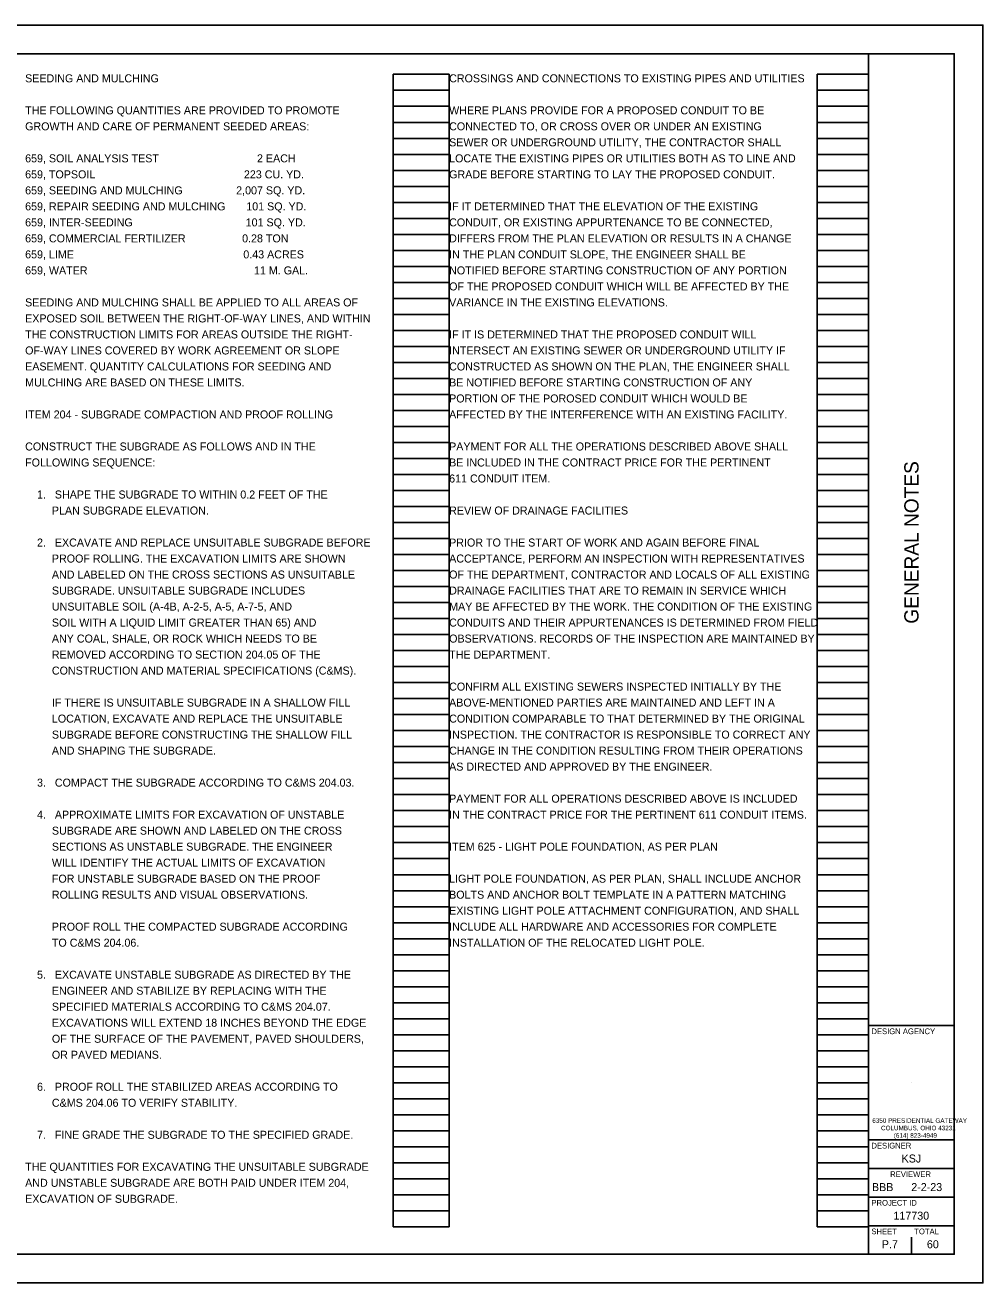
# Model space of a CAD drawing. Extents: x 0 to 68, y 0 to 44.
# Drawn here: x 34.48 to 68, y 0 to 44 of the extents above; entities that cross this region are included whole.
import ezdxf

# ---------------------------------------------------------------- set-up
doc = ezdxf.new("R2010")
doc.units = 0
for name, color, linetype in [('SH_Border', 7, 'Continuous'), ('SH_Cut_Line', 7, 'Continuous'), ('SH_Data', 7, 'Continuous'), ('SH_Text', 7, 'Continuous')]:
    doc.layers.add(name, color=color, linetype=linetype)

msp = doc.modelspace()

# ---------------------------------------------------------------- linework, layer by layer
at = {"layer": 'SH_Border'}
for p, q in [((64, 1), (64, 43)), ((64, 9), (67, 9)), ((64, 5), (67, 5)), ((64, 4), (67, 4)), ((64, 3), (67, 3)), ((64, 2), (67, 2))]:
    msp.add_line(p, q, dxfattribs=at)
msp.add_lwpolyline([(3, 43), (67, 43), (67, 1), (3, 1)], close=True, dxfattribs=at)
at = {"layer": 'SH_Cut_Line'}
msp.add_lwpolyline([(0, 0), (68, 0), (68, 44), (0, 44)], close=True, dxfattribs=at)
at = {"layer": 'SH_Data'}
for p, q in [((47.36, 1.96), (47.36, 42.28)), ((47.36, 42.28), (49.32, 42.28)), ((49.32, 1.96), (49.32, 42.28)), ((62.2, 1.96), (62.2, 42.28)), ((62.2, 42.28), (64, 42.28)), ((64, 1.96), (64, 42.28)), ((47.36, 41.72), (49.32, 41.72)), ((62.2, 41.72), (64, 41.72)), ((47.36, 41.16), (49.32, 41.16)), ((62.2, 41.16), (64, 41.16)), ((47.36, 40.6), (49.32, 40.6)), ((62.2, 40.6), (64, 40.6)), ((47.36, 40.04), (49.32, 40.04)), ((62.2, 40.04), (64, 40.04)), ((47.36, 39.48), (49.32, 39.48)), ((62.2, 39.48), (64, 39.48)), ((47.36, 38.92), (49.32, 38.92)), ((62.2, 38.92), (64, 38.92)), ((47.36, 38.36), (49.32, 38.36)), ((62.2, 38.36), (64, 38.36)), ((47.36, 37.8), (49.32, 37.8)), ((62.2, 37.8), (64, 37.8)), ((47.36, 37.24), (49.32, 37.24)), ((62.2, 37.24), (64, 37.24)), ((47.36, 36.68), (49.32, 36.68)), ((62.2, 36.68), (64, 36.68)), ((47.36, 36.12), (49.32, 36.12)), ((62.2, 36.12), (64, 36.12)), ((47.36, 35.56), (49.32, 35.56)), ((62.2, 35.56), (64, 35.56)), ((47.36, 35), (49.32, 35)), ((62.2, 35), (64, 35)), ((47.36, 34.44), (49.32, 34.44)), ((62.2, 34.44), (64, 34.44)), ((47.36, 33.88), (49.32, 33.88)), ((62.2, 33.88), (64, 33.88)), ((47.36, 33.32), (49.32, 33.32)), ((62.2, 33.32), (64, 33.32)), ((47.36, 32.76), (49.32, 32.76)), ((62.2, 32.76), (64, 32.76)), ((47.36, 32.2), (49.32, 32.2)), ((62.2, 32.2), (64, 32.2)), ((47.36, 31.64), (49.32, 31.64)), ((62.2, 31.64), (64, 31.64)), ((47.36, 31.08), (49.32, 31.08)), ((62.2, 31.08), (64, 31.08)), ((47.36, 30.52), (49.32, 30.52)), ((62.2, 30.52), (64, 30.52)), ((47.36, 29.96), (49.32, 29.96)), ((62.2, 29.96), (64, 29.96)), ((47.36, 29.4), (49.32, 29.4)), ((62.2, 29.4), (64, 29.4)), ((47.36, 28.84), (49.32, 28.84)), ((62.2, 28.84), (64, 28.84)), ((47.36, 28.28), (49.32, 28.28)), ((62.2, 28.28), (64, 28.28)), ((47.36, 27.72), (49.32, 27.72)), ((62.2, 27.72), (64, 27.72)), ((47.36, 27.16), (49.32, 27.16)), ((62.2, 27.16), (64, 27.16)), ((47.36, 26.6), (49.32, 26.6)), ((62.2, 26.6), (64, 26.6)), ((47.36, 26.04), (49.32, 26.04)), ((62.2, 26.04), (64, 26.04)), ((47.36, 25.48), (49.32, 25.48)), ((62.2, 25.48), (64, 25.48)), ((47.36, 24.92), (49.32, 24.92)), ((62.2, 24.92), (64, 24.92)), ((47.36, 24.36), (49.32, 24.36)), ((62.2, 24.36), (64, 24.36)), ((47.36, 23.8), (49.32, 23.8)), ((62.2, 23.8), (64, 23.8)), ((47.36, 23.24), (49.32, 23.24)), ((62.2, 23.24), (64, 23.24)), ((47.36, 22.68), (49.32, 22.68)), ((62.2, 22.68), (64, 22.68)), ((47.36, 22.12), (49.32, 22.12)), ((62.2, 22.12), (64, 22.12)), ((47.36, 21.56), (49.32, 21.56)), ((62.2, 21.56), (64, 21.56)), ((47.36, 21), (49.32, 21)), ((62.2, 21), (64, 21)), ((47.36, 20.44), (49.32, 20.44)), ((62.2, 20.44), (64, 20.44)), ((47.36, 19.88), (49.32, 19.88)), ((62.2, 19.88), (64, 19.88)), ((47.36, 19.32), (49.32, 19.32)), ((62.2, 19.32), (64, 19.32)), ((47.36, 18.76), (49.32, 18.76)), ((62.2, 18.76), (64, 18.76)), ((47.36, 18.2), (49.32, 18.2)), ((62.2, 18.2), (64, 18.2)), ((47.36, 17.64), (49.32, 17.64)), ((62.2, 17.64), (64, 17.64)), ((47.36, 17.08), (49.32, 17.08)), ((62.2, 17.08), (64, 17.08)), ((47.36, 16.52), (49.32, 16.52)), ((62.2, 16.52), (64, 16.52)), ((47.36, 15.96), (49.32, 15.96)), ((62.2, 15.96), (64, 15.96)), ((47.36, 15.4), (49.32, 15.4)), ((62.2, 15.4), (64, 15.4)), ((47.36, 14.84), (49.32, 14.84)), ((62.2, 14.84), (64, 14.84)), ((47.36, 14.28), (49.32, 14.28)), ((62.2, 14.28), (64, 14.28)), ((47.36, 13.72), (49.32, 13.72)), ((62.2, 13.72), (64, 13.72)), ((47.36, 13.16), (49.32, 13.16)), ((62.2, 13.16), (64, 13.16)), ((47.36, 12.6), (49.32, 12.6)), ((62.2, 12.6), (64, 12.6)), ((47.36, 12.04), (49.32, 12.04)), ((62.2, 12.04), (64, 12.04)), ((47.36, 11.48), (49.32, 11.48)), ((62.2, 11.48), (64, 11.48)), ((47.36, 10.92), (49.32, 10.92)), ((62.2, 10.92), (64, 10.92)), ((47.36, 10.36), (49.32, 10.36)), ((62.2, 10.36), (64, 10.36)), ((47.36, 9.8), (49.32, 9.8)), ((62.2, 9.8), (64, 9.8)), ((47.36, 9.24), (49.32, 9.24)), ((62.2, 9.24), (64, 9.24)), ((47.36, 8.68), (49.32, 8.68)), ((62.2, 8.68), (64, 8.68)), ((47.36, 8.12), (49.32, 8.12)), ((62.2, 8.12), (64, 8.12)), ((47.36, 7.56), (49.32, 7.56)), ((62.2, 7.56), (64, 7.56)), ((47.36, 7), (49.32, 7)), ((62.2, 7), (64, 7)), ((65.5, 7), (65.5, 7)), ((47.36, 6.44), (49.32, 6.44)), ((62.2, 6.44), (64, 6.44)), ((47.36, 5.88), (49.32, 5.88)), ((62.2, 5.88), (64, 5.88)), ((47.36, 5.32), (49.32, 5.32)), ((62.2, 5.32), (64, 5.32)), ((47.36, 4.76), (49.32, 4.76)), ((62.2, 4.76), (64, 4.76)), ((47.36, 4.2), (49.32, 4.2)), ((62.2, 4.2), (64, 4.2)), ((47.36, 3.64), (49.32, 3.64)), ((62.2, 3.64), (64, 3.64)), ((47.36, 3.08), (49.32, 3.08)), ((62.2, 3.08), (64, 3.08)), ((47.36, 2.52), (49.32, 2.52)), ((62.2, 2.52), (64, 2.52)), ((47.36, 1.96), (49.32, 1.96)), ((62.2, 1.96), (64, 1.96)), ((64.75, 1.35), (64.75, 1.35)), ((65.5, 1), (65.5, 1.6))]:
    msp.add_line(p, q, dxfattribs=at)
at = {"layer": 'SH_Text'}
msp.add_line((64, 9), (67, 9), dxfattribs=at)

# ---------------------------------------------------------------- texts
at = {"layer": 'SH_Data'}
msp.add_text('GENERAL NOTES', height=0.5, rotation=90, dxfattribs=at).set_placement((65.75, 23.061))
for s, height, p in [('DESIGN AGENCY', 0.2, (64.1, 8.7)), ('6350 PRESIDENTIAL GATEWAY', 0.16, (64.13, 5.597)), ('COLUMBUS, OHIO 43231', 0.16, (64.436, 5.337)), ('DESIGNER', 0.2, (64.1, 4.7)), ('(614) 823-4949', 0.16, (64.882, 5.077)), ('KSJ', 0.28, (65.156, 4.21)), ('REVIEWER', 0.2, (64.757, 3.7)), ('BBB', 0.28, (64.119, 3.21)), ('2-2-23', 0.28, (65.494, 3.21)), ('PROJECT ID', 0.2, (64.1, 2.7)), ('117730', 0.28, (64.871, 2.21)), ('SHEET', 0.2, (64.1, 1.7)), ('TOTAL', 0.2, (65.6, 1.7)), ('P.7', 0.28, (64.465, 1.21)), ('60', 0.28, (66.042, 1.21))]:
    msp.add_text(s, height=height, dxfattribs=at).set_placement(p)
at = {"layer": 'SH_Text'}
for s, p in [('SEEDING AND MULCHING', (34.48, 42)), ('CROSSINGS AND CONNECTIONS TO EXISTING PIPES AND UTILITIES', (49.32, 42)), ('THE FOLLOWING QUANTITIES ARE PROVIDED TO PROMOTE', (34.48, 40.88)), ('WHERE PLANS PROVIDE FOR A PROPOSED CONDUIT TO BE', (49.32, 40.88)), ('GROWTH AND CARE OF PERMANENT SEEDED AREAS:', (34.48, 40.32)), ('CONNECTED TO, OR CROSS OVER OR UNDER AN EXISTING', (49.32, 40.32)), ('SEWER OR UNDERGROUND UTILITY, THE CONTRACTOR SHALL', (49.32, 39.76)), ('659, SOIL ANALYSIS TEST                                 2 EACH', (34.48, 39.2)), ('LOCATE THE EXISTING PIPES OR UTILITIES BOTH AS TO LINE AND', (49.32, 39.2)), ('659, TOPSOIL                                                  223 CU. YD.', (34.48, 38.64)), ('GRADE BEFORE STARTING TO LAY THE PROPOSED CONDUIT.', (49.32, 38.64)), ('659, SEEDING AND MULCHING                  2,007 SQ. YD.', (34.48, 38.08)), ('659, REPAIR SEEDING AND MULCHING       101 SQ. YD.', (34.48, 37.52)), ('IF IT DETERMINED THAT THE ELEVATION OF THE EXISTING', (49.32, 37.52)), ('659, INTER-SEEDING                                      101 SQ. YD.', (34.48, 36.96)), ('CONDUIT, OR EXISTING APPURTENANCE TO BE CONNECTED,', (49.32, 36.96)), ('659, COMMERCIAL FERTILIZER                   0.28 TON', (34.48, 36.4)), ('DIFFERS FROM THE PLAN ELEVATION OR RESULTS IN A CHANGE', (49.32, 36.4)), ('659, LIME                                                         0.43 ACRES', (34.48, 35.84)), ('IN THE PLAN CONDUIT SLOPE, THE ENGINEER SHALL BE', (49.32, 35.84)), ('659, WATER                                                        11 M. GAL.', (34.48, 35.28)), ('NOTIFIED BEFORE STARTING CONSTRUCTION OF ANY PORTION', (49.32, 35.28)), ('OF THE PROPOSED CONDUIT WHICH WILL BE AFFECTED BY THE', (49.32, 34.72)), ('SEEDING AND MULCHING SHALL BE APPLIED TO ALL AREAS OF', (34.48, 34.16)), ('VARIANCE IN THE EXISTING ELEVATIONS.', (49.32, 34.16)), ('EXPOSED SOIL BETWEEN THE RIGHT-OF-WAY LINES, AND WITHIN ', (34.48, 33.6)), ('THE CONSTRUCTION LIMITS FOR AREAS OUTSIDE THE RIGHT-', (34.48, 33.04)), ('IF IT IS DETERMINED THAT THE PROPOSED CONDUIT WILL', (49.32, 33.04)), ('OF-WAY LINES COVERED BY WORK AGREEMENT OR SLOPE', (34.48, 32.48)), ('INTERSECT AN EXISTING SEWER OR UNDERGROUND UTILITY IF', (49.32, 32.48)), ('EASEMENT. QUANTITY CALCULATIONS FOR SEEDING AND ', (34.48, 31.92)), ('CONSTRUCTED AS SHOWN ON THE PLAN, THE ENGINEER SHALL', (49.32, 31.92)), ('MULCHING ARE BASED ON THESE LIMITS.', (34.48, 31.36)), ('BE NOTIFIED BEFORE STARTING CONSTRUCTION OF ANY', (49.32, 31.36)), ('PORTION OF THE POROSED CONDUIT WHICH WOULD BE', (49.32, 30.8)), ('ITEM 204 - SUBGRADE COMPACTION AND PROOF ROLLING', (34.48, 30.24)), ('AFFECTED BY THE INTERFERENCE WITH AN EXISTING FACILITY.', (49.32, 30.24)), ('CONSTRUCT THE SUBGRADE AS FOLLOWS AND IN THE', (34.48, 29.12)), ('PAYMENT FOR ALL THE OPERATIONS DESCRIBED ABOVE SHALL', (49.32, 29.12)), ('FOLLOWING SEQUENCE:', (34.48, 28.56)), ('BE INCLUDED IN THE CONTRACT PRICE FOR THE PERTINENT', (49.32, 28.56)), ('611 CONDUIT ITEM.', (49.32, 28)), ('    1.   SHAPE THE SUBGRADE TO WITHIN 0.2 FEET OF THE', (34.48, 27.44)), ('         PLAN SUBGRADE ELEVATION.', (34.48, 26.88)), ('REVIEW OF DRAINAGE FACILITIES', (49.32, 26.88)), ('    2.   EXCAVATE AND REPLACE UNSUITABLE SUBGRADE BEFORE ', (34.48, 25.76)), ('PRIOR TO THE START OF WORK AND AGAIN BEFORE FINAL ', (49.32, 25.76)), ('         PROOF ROLLING. THE EXCAVATION LIMITS ARE SHOWN', (34.48, 25.2)), ('ACCEPTANCE, PERFORM AN INSPECTION WITH REPRESENTATIVES ', (49.32, 25.2)), ('         AND LABELED ON THE CROSS SECTIONS AS UNSUITABLE ', (34.48, 24.64)), ('OF THE DEPARTMENT, CONTRACTOR AND LOCALS OF ALL EXISTING ', (49.32, 24.64)), ('         SUBGRADE. UNSUITABLE SUBGRADE INCLUDES ', (34.48, 24.08)), ('DRAINAGE FACILITIES THAT ARE TO REMAIN IN SERVICE WHICH ', (49.32, 24.08)), ('         UNSUITABLE SOIL (A-4B, A-2-5, A-5, A-7-5, AND ', (34.48, 23.52)), ('MAY BE AFFECTED BY THE WORK. THE CONDITION OF THE EXISTING ', (49.32, 23.52)), ('         SOIL WITH A LIQUID LIMIT GREATER THAN 65) AND', (34.48, 22.96)), ('CONDUITS AND THEIR APPURTENANCES IS DETERMINED FROM FIELD ', (49.32, 22.96)), ('         ANY COAL, SHALE, OR ROCK WHICH NEEDS TO BE', (34.48, 22.4)), ('OBSERVATIONS. RECORDS OF THE INSPECTION ARE MAINTAINED BY ', (49.32, 22.4)), ('         REMOVED ACCORDING TO SECTION 204.05 OF THE', (34.48, 21.84)), ('THE DEPARTMENT.', (49.32, 21.84)), ('         CONSTRUCTION AND MATERIAL SPECIFICATIONS (C&MS).', (34.48, 21.28)), ('CONFIRM ALL EXISTING SEWERS INSPECTED INITIALLY BY THE ', (49.32, 20.72)), ('         IF THERE IS UNSUITABLE SUBGRADE IN A SHALLOW FILL ', (34.48, 20.16)), ('ABOVE-MENTIONED PARTIES ARE MAINTAINED AND LEFT IN A ', (49.32, 20.16)), ('         LOCATION, EXCAVATE AND REPLACE THE UNSUITABLE ', (34.48, 19.6)), ('CONDITION COMPARABLE TO THAT DETERMINED BY THE ORIGINAL ', (49.32, 19.6)), ('         SUBGRADE BEFORE CONSTRUCTING THE SHALLOW FILL ', (34.48, 19.04)), ('INSPECTION. THE CONTRACTOR IS RESPONSIBLE TO CORRECT ANY ', (49.32, 19.04)), ('         AND SHAPING THE SUBGRADE.', (34.48, 18.48)), ('CHANGE IN THE CONDITION RESULTING FROM THEIR OPERATIONS ', (49.32, 18.48)), ('AS DIRECTED AND APPROVED BY THE ENGINEER.', (49.32, 17.92)), ('    3.   COMPACT THE SUBGRADE ACCORDING TO C&MS 204.03.', (34.48, 17.36)), ('PAYMENT FOR ALL OPERATIONS DESCRIBED ABOVE IS INCLUDED ', (49.32, 16.8)), ('    4.   APPROXIMATE LIMITS FOR EXCAVATION OF UNSTABLE ', (34.48, 16.24)), ('IN THE CONTRACT PRICE FOR THE PERTINENT 611 CONDUIT ITEMS.', (49.32, 16.24)), ('         SUBGRADE ARE SHOWN AND LABELED ON THE CROSS ', (34.48, 15.68)), ('         SECTIONS AS UNSTABLE SUBGRADE. THE ENGINEER  ', (34.48, 15.12)), ('ITEM 625 - LIGHT POLE FOUNDATION, AS PER PLAN', (49.32, 15.12)), ('         WILL IDENTIFY THE ACTUAL LIMITS OF EXCAVATION ', (34.48, 14.56)), ('         FOR UNSTABLE SUBGRADE BASED ON THE PROOF ', (34.48, 14)), ('LIGHT POLE FOUNDATION, AS PER PLAN, SHALL INCLUDE ANCHOR', (49.32, 14)), ('         ROLLING RESULTS AND VISUAL OBSERVATIONS.', (34.48, 13.44)), ('BOLTS AND ANCHOR BOLT TEMPLATE IN A PATTERN MATCHING', (49.32, 13.44)), ('EXISTING LIGHT POLE ATTACHMENT CONFIGURATION, AND SHALL', (49.32, 12.88)), ('         PROOF ROLL THE COMPACTED SUBGRADE ACCORDING', (34.48, 12.32)), ('INCLUDE ALL HARDWARE AND ACCESSORIES FOR COMPLETE', (49.32, 12.32)), ('         TO C&MS 204.06.', (34.48, 11.76)), ('INSTALLATION OF THE RELOCATED LIGHT POLE.', (49.32, 11.76)), ('    5.   EXCAVATE UNSTABLE SUBGRADE AS DIRECTED BY THE ', (34.48, 10.64)), ('         ENGINEER AND STABILIZE BY REPLACING WITH THE ', (34.48, 10.08)), ('         SPECIFIED MATERIALS ACCORDING TO C&MS 204.07. ', (34.48, 9.52)), ('         EXCAVATIONS WILL EXTEND 18 INCHES BEYOND THE EDGE ', (34.48, 8.96)), ('         OF THE SURFACE OF THE PAVEMENT, PAVED SHOULDERS, ', (34.48, 8.4)), ('         OR PAVED MEDIANS.', (34.48, 7.84)), ('    6.   PROOF ROLL THE STABILIZED AREAS ACCORDING TO', (34.48, 6.72)), ('         C&MS 204.06 TO VERIFY STABILITY.', (34.48, 6.16)), ('    7.   FINE GRADE THE SUBGRADE TO THE SPECIFIED GRADE.', (34.48, 5.04)), ('THE QUANTITIES FOR EXCAVATING THE UNSUITABLE SUBGRADE ', (34.48, 3.92)), ('AND UNSTABLE SUBGRADE ARE BOTH PAID UNDER ITEM 204,', (34.48, 3.36)), ('EXCAVATION OF SUBGRADE.', (34.48, 2.8))]:
    msp.add_text(s, height=0.28, dxfattribs=at).set_placement(p)

doc.saveas('drawing.dxf')
